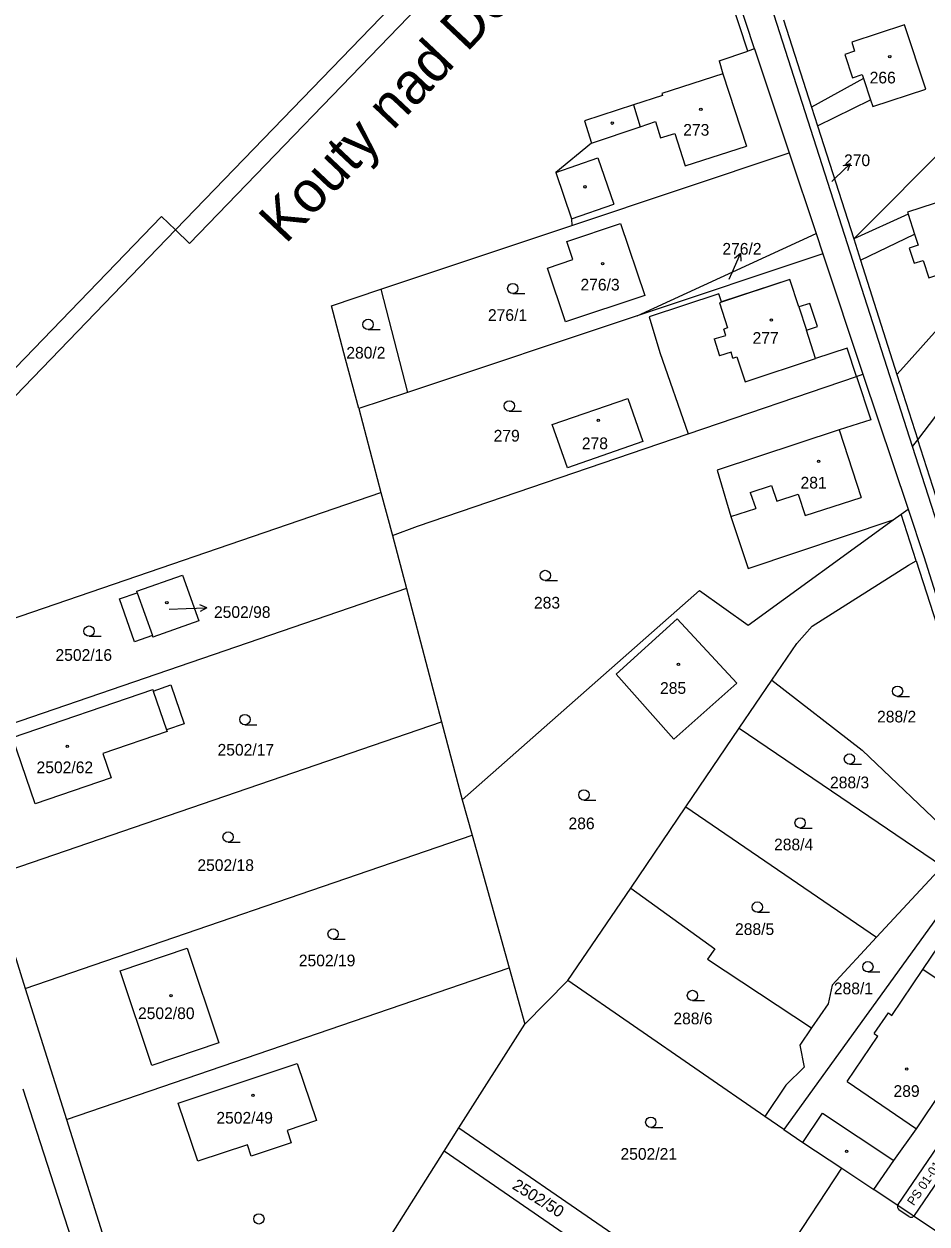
# Model space of a CAD drawing. Extents: x -558500 to -557517, y -1073973 to -1073051.
# Drawn here: x -558300.8 to -558169.6, y -1073407.4 to -1073232.9 of the extents above; entities that cross this region are included whole.
import ezdxf

# ---------------------------------------------------------------- set-up
doc = ezdxf.new("R2010")
doc.units = 0
for name, color, linetype in [('bubliny', 7, 'Continuous'), ('Hranice parcel', 7, 'Continuous'), ('Parcelní čísla', 7, 'Continuous'), ('Pop  PČ popisy', 7, 'Continuous'), ('Vnitřní kresba', 7, 'Continuous'), ('Vrstva 1', 7, 'Continuous'), ('Značky budov', 7, 'Continuous'), ('Značky kultur', 7, 'Continuous')]:
    doc.layers.add(name, color=color, linetype=linetype)

msp = doc.modelspace()

# ---------------------------------------------------------------- linework, layer by layer
at = {"layer": 'bubliny'}
for points in [[(-558173.82, -1073404.58), (-558168.09, -1073396.16)], [(-558165.75, -1073397.76), (-558171.48, -1073406.18)], [(-558172.27, -1073406.32), (-558173.67, -1073405.37)]]:
    msp.add_lwpolyline(points, dxfattribs=at)
for centre, start, end in [((-558173.35, -1073404.9), 145.7688, 235.7688), ((-558171.95, -1073405.86), 235.7688, 325.7688)]:
    msp.add_arc(centre, 0.566, start, end, dxfattribs=at)
at = {"layer": 'Hranice parcel'}
for p, q in [((-558195.64, -1073236.88), (-558206.21, -1073204.6)), ((-558171.71, -1073294.39), (-558199.08, -1073209.06)), ((-558190.48, -1073232.36), (-558186.42, -1073245.02)), ((-558180.27, -1073264.19), (-558150.02, -1073233.76)), ((-558194.69, -1073236.56), (-558195.64, -1073236.88)), ((-558194.69, -1073236.56), (-558189.64, -1073251.69)), ((-558199.8, -1073238.31), (-558195.64, -1073236.88)), ((-558186.42, -1073245.02), (-558185.55, -1073247.73)), ((-558185.55, -1073247.73), (-558180.27, -1073264.19)), ((-558221.22, -1073262.24), (-558189.64, -1073251.69)), ((-558189.64, -1073251.69), (-558185.73, -1073263.4)), ((-558248.97, -1073271.5), (-558221.22, -1073262.24)), ((-558211.74, -1073275.38), (-558185.73, -1073263.4)), ((-558185.73, -1073263.4), (-558184.74, -1073266.37)), ((-558180.27, -1073264.19), (-558179.28, -1073267.3)), ((-558184.74, -1073266.37), (-558211.74, -1073275.38)), ((-558184.74, -1073266.37), (-558178.92, -1073283.85)), ((-558179.28, -1073267.3), (-558173.98, -1073283.88)), ((-558256.16, -1073273.9), (-558248.97, -1073271.5)), ((-558248.97, -1073271.5), (-558245.1, -1073286.51)), ((-558254.1, -1073281.66), (-558256.16, -1073273.9)), ((-558185.53, -1073276.94), (-558186.65, -1073273.58)), ((-558211.74, -1073275.38), (-558245.1, -1073286.51)), ((-558252.2, -1073288.86), (-558254.1, -1073281.66)), ((-558179.86, -1073284.17), (-558178.92, -1073283.85)), ((-558178.92, -1073283.85), (-558172.36, -1073303.47)), ((-558170.97, -1073293.42), (-558163.02, -1073282.94)), ((-558204.33, -1073292.51), (-558179.86, -1073284.17)), ((-558173.98, -1073283.88), (-558170.97, -1073293.42)), ((-558245.1, -1073286.51), (-558252.2, -1073288.86)), ((-558252.2, -1073288.86), (-558248.97, -1073301.04)), ((-558171.71, -1073294.39), (-558170.97, -1073293.42)), ((-558161.8, -1073321.91), (-558170.97, -1073293.42)), ((-558313.8, -1073323.28), (-558248.97, -1073301.04)), ((-558248.97, -1073301.04), (-558247.31, -1073307.29)), ((-558174.53, -1073305.05), (-558173.36, -1073304.2)), ((-558173.36, -1073304.2), (-558172.36, -1073303.47)), ((-558171.18, -1073310.99), (-558173.36, -1073304.2)), ((-558247.31, -1073307.29), (-558245.27, -1073315.03)), ((-558171.18, -1073310.99), (-558158.75, -1073349.79)), ((-558245.27, -1073315.03), (-558311.02, -1073337.58)), ((-558245.27, -1073315.03), (-558240.15, -1073334.41)), ((-558196.91, -1073335.32), (-558192.17, -1073328.33)), ((-558192.17, -1073328.33), (-558179.03, -1073338.54)), ((-558305.76, -1073356.92), (-558240.15, -1073334.41)), ((-558240.15, -1073334.41), (-558237.16, -1073345.74)), ((-558204.65, -1073346.74), (-558196.91, -1073335.32)), ((-558196.91, -1073335.32), (-558167.35, -1073355.36)), ((-558179.03, -1073338.54), (-558163.3, -1073353.56)), ((-558237.16, -1073345.74), (-558235.73, -1073350.87)), ((-558212.67, -1073358.56), (-558204.65, -1073346.74)), ((-558204.65, -1073346.74), (-558176.94, -1073365.71)), ((-558158.75, -1073349.79), (-558190.43, -1073393.65)), ((-558300.65, -1073373.14), (-558235.73, -1073350.87)), ((-558235.73, -1073350.87), (-558230.35, -1073370.17)), ((-558167.35, -1073355.36), (-558176.94, -1073365.71)), ((-558305.76, -1073356.92), (-558300.65, -1073373.14)), ((-558221.79, -1073372.01), (-558212.67, -1073358.56)), ((-558212.67, -1073358.56), (-558200.47, -1073367.38)), ((-558294.64, -1073392.22), (-558230.35, -1073370.17)), ((-558230.35, -1073370.17), (-558228.07, -1073378.34)), ((-558228.07, -1073378.34), (-558221.79, -1073372.01)), ((-558193.18, -1073391.75), (-558221.79, -1073372.01)), ((-558300.65, -1073373.14), (-558294.64, -1073392.22)), ((-558237.63, -1073393.44), (-558228.07, -1073378.34)), ((-558190.12, -1073387.22), (-558193.18, -1073391.75)), ((-558190.43, -1073393.65), (-558193.18, -1073391.75)), ((-558294.64, -1073392.22), (-558288.18, -1073412.71)), ((-558239.77, -1073396.82), (-558237.63, -1073393.44)), ((-558237.63, -1073393.44), (-558213.88, -1073409.79)), ((-558257.7, -1073425.14), (-558239.77, -1073396.82)), ((-558216.02, -1073413.17), (-558239.77, -1073396.82)), ((-558196.71, -1073421.6), (-558181.99, -1073399.3)), ((-558181.99, -1073399.3), (-558177.33, -1073402.38)), ((-558166.05, -1073409.92), (-558177.33, -1073402.38))]:
    msp.add_line(p, q, dxfattribs=at)
for points in [[(-558194.69, -1073236.56), (-558230.74, -1073126.95), (-558255.65, -1073051.21)], [(-558185.55, -1073247.73), (-558177.82, -1073243.95), (-558177.49, -1073244.94), (-558169.79, -1073242.44), (-558172.9, -1073233.07), (-558180.56, -1073235.6), (-558180.13, -1073236.92), (-558181.54, -1073237.39), (-558180.43, -1073240.78), (-558179.03, -1073240.27), (-558178.83, -1073240.86), (-558186.42, -1073245.02)], [(-558199.8, -1073238.31), (-558199.29, -1073240.2), (-558208.14, -1073243.05), (-558208.05, -1073243.33), (-558212.29, -1073244.72), (-558219.4, -1073247.05), (-558218.39, -1073250.28), (-558223.57, -1073254.53), (-558221.27, -1073261.29), (-558221.22, -1073262.24)], [(-558140.75, -1073241.36), (-558158.68, -1073266.81), (-558173.01, -1073282.83), (-558173.98, -1073283.88)], [(-558179.28, -1073267.3), (-558171.41, -1073263.5), (-558170.89, -1073265.11), (-558172.23, -1073265.52), (-558171.5, -1073267.74), (-558170.17, -1073267.35), (-558169.36, -1073269.84), (-558161.57, -1073267.22), (-558164.69, -1073257.79), (-558172.45, -1073260.31), (-558172.35, -1073260.6), (-558180.27, -1073264.19)], [(-558210.64, -1073272.4), (-558222.13, -1073276.25), (-558224.75, -1073268.45), (-558221.07, -1073267.2), (-558221.97, -1073264.55), (-558214.15, -1073261.94), (-558210.64, -1073272.4)], [(-558186.65, -1073273.58), (-558188.24, -1073274.09), (-558189.55, -1073270.09), (-558199.49, -1073273.33), (-558199.86, -1073272.19), (-558209.99, -1073275.5), (-558208.43, -1073280.69), (-558204.33, -1073292.51)], [(-558179.86, -1073284.17), (-558181.24, -1073280.09), (-558185.8, -1073281.59), (-558187.15, -1073277.46), (-558185.53, -1073276.94)], [(-558179.86, -1073284.17), (-558177.8, -1073290.48), (-558182.36, -1073291.97), (-558200.11, -1073297.8), (-558198.12, -1073304.57), (-558195.6, -1073312.09), (-558174.53, -1073305.05)], [(-558210.92, -1073293.66), (-558221.88, -1073297.46), (-558224.1, -1073291.16), (-558213.08, -1073287.38), (-558210.92, -1073293.66)], [(-558247.31, -1073307.29), (-558243.66, -1073305.93), (-558204.33, -1073292.51)], [(-558140.29, -1073392.34), (-558154.66, -1073347.35), (-558171.71, -1073294.39)], [(-558172.36, -1073303.47), (-558170.06, -1073310.34), (-558157.85, -1073349.12), (-558143.83, -1073396.83)], [(-558237.16, -1073345.74), (-558202.67, -1073315.29), (-558195.58, -1073320.33), (-558174.53, -1073305.05)], [(-558192.17, -1073328.33), (-558188.55, -1073322.99), (-558186.3, -1073320.49), (-558172.32, -1073311.63), (-558171.18, -1073310.99)], [(-558275.45, -1073319.73), (-558282.1, -1073322.07), (-558282.17, -1073321.87), (-558284.8, -1073322.78), (-558286.97, -1073316.53), (-558284.37, -1073315.62), (-558284.44, -1073315.41), (-558277.79, -1073313.08), (-558275.45, -1073319.73)], [(-558197.27, -1073328.8), (-558205.94, -1073319.43), (-558214.79, -1073327.48), (-558206.42, -1073336.91), (-558197.27, -1073328.8)], [(-558302.49, -1073336.69), (-558282.13, -1073329.71), (-558282.06, -1073329.92), (-558279.49, -1073329.04), (-558277.55, -1073334.7), (-558280.12, -1073335.56), (-558280.04, -1073335.79), (-558289.36, -1073338.99), (-558288.15, -1073342.54), (-558299.21, -1073346.34), (-558302.49, -1073336.69)], [(-558176.94, -1073365.71), (-558183.41, -1073372.7), (-558183.98, -1073375.4), (-558186.39, -1073378.87)], [(-558167.71, -1073372.11), (-558170.24, -1073370.42), (-558166.77, -1073365.3)], [(-558282.25, -1073384.34), (-558286.86, -1073370.59), (-558277.14, -1073367.32), (-558272.5, -1073381.07), (-558282.25, -1073384.34)], [(-558200.47, -1073367.38), (-558201.52, -1073368.91), (-558186.39, -1073378.87)], [(-558177.33, -1073402.38), (-558174.43, -1073398.17), (-558171.12, -1073393.55), (-558160.15, -1073377.12)], [(-558186.39, -1073378.87), (-558188.11, -1073381.41), (-558187.47, -1073384.59), (-558190.12, -1073387.22)], [(-558278.42, -1073389.81), (-558261.13, -1073384.05), (-558258.31, -1073392.37), (-558262.58, -1073393.82), (-558262, -1073395.6), (-558267.81, -1073397.55), (-558268.37, -1073395.87), (-558275.59, -1073398.26), (-558278.42, -1073389.81)], [(-558301.02, -1073387.75), (-558291.95, -1073415.8), (-558291.74, -1073416.28)], [(-558190.43, -1073393.65), (-558187.68, -1073395.55), (-558181.99, -1073399.3)]]:
    msp.add_lwpolyline(points, dxfattribs=at)
at = {"layer": 'Pop  PČ popisy'}
for p, q in [((-558182.95, -1073255.34), (-558180.79, -1073253.26)), ((-558180.79, -1073253.26), (-558181.86, -1073253.59)), ((-558180.79, -1073253.26), (-558181.16, -1073254.31)), ((-558183.46, -1073255.83), (-558182.95, -1073255.34)), ((-558197.94, -1073269.07), (-558196.72, -1073266.33)), ((-558196.72, -1073266.33), (-558197.58, -1073267.04)), ((-558196.72, -1073266.33), (-558196.67, -1073267.45)), ((-558198.36, -1073270.02), (-558197.94, -1073269.07)), ((-558279.76, -1073318.04), (-558277.28, -1073317.94)), ((-558277.28, -1073317.94), (-558274.28, -1073317.83)), ((-558274.28, -1073317.83), (-558275.3, -1073317.37)), ((-558274.28, -1073317.83), (-558275.26, -1073318.37))]:
    msp.add_line(p, q, dxfattribs=at)
at = {"layer": 'Vnitřní kresba'}
for p, q in [((-558199.29, -1073240.2), (-558195.85, -1073250.73)), ((-558178.83, -1073240.86), (-558177.82, -1073243.95)), ((-558212.29, -1073244.72), (-558211.3, -1073247.89)), ((-558211.3, -1073247.89), (-558209.09, -1073247.14)), ((-558209.09, -1073247.14), (-558208.34, -1073249.51)), ((-558218.39, -1073250.28), (-558211.3, -1073247.89)), ((-558208.34, -1073249.51), (-558206.26, -1073248.85)), ((-558206.26, -1073248.85), (-558204.74, -1073253.59)), ((-558223.57, -1073254.53), (-558217.44, -1073252.39)), ((-558217.44, -1073252.39), (-558215.14, -1073259.16)), ((-558204.74, -1073253.59), (-558195.85, -1073250.73)), ((-558221.27, -1073261.29), (-558215.14, -1073259.16)), ((-558172.35, -1073260.6), (-558171.41, -1073263.5)), ((-558189.55, -1073270.09), (-558199.78, -1073273.49)), ((-558199.78, -1073273.49), (-558198.6, -1073277.11)), ((-558188.24, -1073274.09), (-558187.15, -1073277.46)), ((-558198.6, -1073277.11), (-558199.14, -1073277.31)), ((-558200.56, -1073278.74), (-558199.78, -1073281.19)), ((-558197.83, -1073281.52), (-558197.23, -1073281.35)), ((-558197.23, -1073281.35), (-558196.05, -1073284.95)), ((-558196.05, -1073284.95), (-558185.8, -1073281.59)), ((-558182.36, -1073291.97), (-558179.17, -1073301.77)), ((-558195.29, -1073301.04), (-558192.22, -1073300.02)), ((-558195.29, -1073301.04), (-558194.51, -1073303.36)), ((-558192.22, -1073300.02), (-558191.45, -1073302.33)), ((-558191.45, -1073302.33), (-558188.34, -1073301.29)), ((-558188.34, -1073301.29), (-558187.3, -1073304.42)), ((-558187.3, -1073304.42), (-558179.17, -1073301.77)), ((-558198.12, -1073304.57), (-558194.51, -1073303.36)), ((-558284.37, -1073315.62), (-558282.17, -1073321.87)), ((-558282.06, -1073329.92), (-558280.12, -1073335.56)), ((-558174.74, -1073377.09), (-558170.24, -1073370.42)), ((-558177.27, -1073379.73), (-558175.23, -1073376.72)), ((-558175.23, -1073376.72), (-558174.74, -1073377.09)), ((-558177.27, -1073379.73), (-558176.76, -1073380.07)), ((-558181.24, -1073386.7), (-558176.76, -1073380.07)), ((-558181.24, -1073386.7), (-558171.12, -1073393.55)), ((-558187.68, -1073395.55), (-558184.81, -1073391.28)), ((-558184.81, -1073391.28), (-558174.43, -1073398.17))]:
    msp.add_line(p, q, dxfattribs=at)
for points in [[(-558200.56, -1073278.74), (-558198.86, -1073278.21), (-558199.14, -1073277.31)], [(-558197.83, -1073281.52), (-558198.09, -1073280.68), (-558199.78, -1073281.19)]]:
    msp.add_lwpolyline(points, dxfattribs=at)
at = {"layer": 'Vrstva 1'}
for p, q in [((-558230.95, -1073213.27), (-558278.82, -1073262.89)), ((-558276.78, -1073264.86), (-558228.09, -1073214.39)), ((-558280.86, -1073260.92), (-558348.4, -1073330.92)), ((-558278.82, -1073262.89), (-558280.86, -1073260.92)), ((-558345.54, -1073332.05), (-558278.82, -1073262.89)), ((-558278.82, -1073262.89), (-558276.78, -1073264.86))]:
    msp.add_line(p, q, dxfattribs=at)
at = {"layer": 'Značky budov'}
for centre in [(-558175.02, -1073237.7), (-558202.48, -1073245.34), (-558215.35, -1073247.36), (-558219.32, -1073256.62), (-558216.76, -1073267.78), (-558192.23, -1073275.99), (-558217.39, -1073290.55), (-558185.37, -1073296.51), (-558280.08, -1073317.09), (-558205.73, -1073326.02), (-558294.55, -1073337.97), (-558279.47, -1073374.21), (-558172.57, -1073384.87), (-558267.57, -1073388.69), (-558181.29, -1073396.84)]:
    msp.add_circle(centre, 0.175, dxfattribs=at)
at = {"layer": 'Značky kultur'}
for p, q in [((-558229.81, -1073272.15), (-558228.06, -1073272.15)), ((-558250.84, -1073277.37), (-558249.09, -1073277.37)), ((-558230.31, -1073289.22), (-558228.56, -1073289.22)), ((-558225.08, -1073313.87), (-558223.33, -1073313.87)), ((-558291.38, -1073321.96), (-558289.63, -1073321.96)), ((-558173.9, -1073330.7), (-558172.15, -1073330.7)), ((-558268.73, -1073334.82), (-558266.98, -1073334.82)), ((-558180.88, -1073340.55), (-558179.13, -1073340.55)), ((-558219.47, -1073345.78), (-558217.72, -1073345.78)), ((-558188.05, -1073349.84), (-558186.3, -1073349.84)), ((-558271.17, -1073351.89), (-558269.42, -1073351.89)), ((-558194.27, -1073362.07), (-558192.52, -1073362.07)), ((-558255.92, -1073365.99), (-558254.17, -1073365.99)), ((-558178.21, -1073370.75), (-558176.46, -1073370.75)), ((-558203.7, -1073374.92), (-558201.95, -1073374.92)), ((-558209.75, -1073393.36), (-558208, -1073393.36))]:
    msp.add_line(p, q, dxfattribs=at)
for centre in [(-558229.81, -1073271.4), (-558250.84, -1073276.62), (-558230.31, -1073288.47), (-558225.08, -1073313.12), (-558291.38, -1073321.21), (-558173.9, -1073329.95), (-558268.73, -1073334.07), (-558180.88, -1073339.8), (-558219.47, -1073345.03), (-558188.05, -1073349.09), (-558271.17, -1073351.14), (-558194.27, -1073361.32), (-558255.92, -1073365.24), (-558178.21, -1073370), (-558203.7, -1073374.17), (-558209.75, -1073392.61), (-558266.71, -1073406.65)]:
    msp.add_circle(centre, 0.75, dxfattribs=at)

# ---------------------------------------------------------------- texts
at = {"layer": 'bubliny'}
msp.add_text('PS 01-01-34', height=1.2994, rotation=55.7688, dxfattribs=at).set_placement((-558171.53, -1073404.84))
at = {"layer": 'Parcelní čísla'}
for s, p in [('266', (-558177.95, -1073241.59)), ('273', (-558205.04, -1073249.19)), ('270', (-558181.67, -1073253.61)), ('276/2', (-558199.35, -1073266.48)), ('276/3', (-558219.97, -1073271.69)), ('276/1', (-558233.42, -1073276.11)), ('277', (-558194.96, -1073279.44)), ('280/2', (-558254, -1073281.59)), ('279', (-558232.59, -1073293.65)), ('278', (-558219.77, -1073294.76)), ('281', (-558187.99, -1073300.48)), ('283', (-558226.73, -1073317.93)), ('2502/98', (-558273.23, -1073319.29)), ('2502/16', (-558296.26, -1073325.53)), ('285', (-558208.41, -1073330.33)), ('288/2', (-558176.87, -1073334.49)), ('2502/17', (-558272.71, -1073339.31)), ('2502/62', (-558299.01, -1073341.86)), ('288/3', (-558183.71, -1073344.06)), ('286', (-558221.71, -1073350.01)), ('288/4', (-558191.84, -1073353.08)), ('2502/18', (-558275.64, -1073356.08)), ('288/5', (-558197.51, -1073365.38)), ('2502/19', (-558260.9, -1073369.94)), ('288/1', (-558183.15, -1073374)), ('2502/80', (-558284.27, -1073377.61)), ('288/6', (-558206.47, -1073378.37)), ('289', (-558174.48, -1073388.92)), ('2502/49', (-558272.88, -1073392.81)), ('2502/21', (-558214.16, -1073398.06))]:
    msp.add_text(s, height=1.7, dxfattribs=at).set_placement(p)
msp.add_text('2502/50', height=1.7, rotation=328, dxfattribs=at).set_placement((-558230.02, -1073402.18))
at = {"layer": 'Vrstva 1'}
msp.add_text('Kouty nad Desnou', height=6, rotation=46.6457, dxfattribs=at).set_placement((-558262.82, -1073265.06))

doc.saveas('drawing.dxf')
